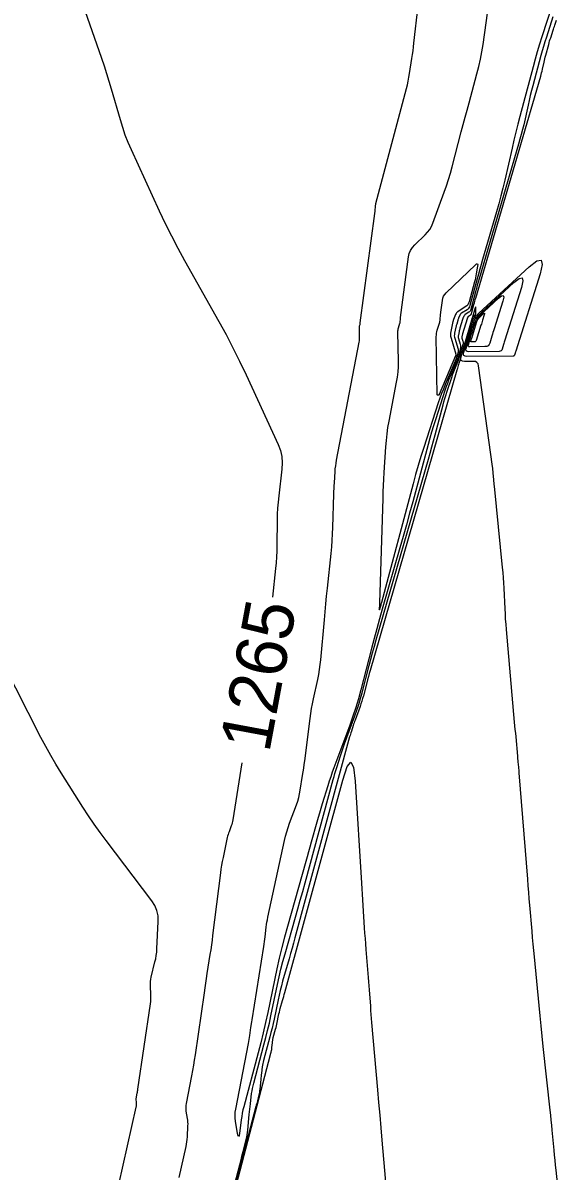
# Model space of a CAD drawing. Extents: x 658976 to 668726, y 639543 to 647196.
# Drawn here: x 661495.3 to 661559.5, y 640947.8 to 641084 of the extents above; entities that cross this region are included whole.
import ezdxf

# ---------------------------------------------------------------- set-up
doc = ezdxf.new("R2010")
doc.units = 0
for name, color, linetype in [('Ex_Contour Labels', 7, 'Continuous'), ('Ex_Major Contours', 7, 'Continuous'), ('Ex_Minor Contours', 7, 'Continuous')]:
    doc.layers.add(name, color=color, linetype=linetype)

msp = doc.modelspace()

# ---------------------------------------------------------------- linework, layer by layer
at = {"layer": 'Ex_Major Contours'}
for points in [[(661498.99, 641096.02), (661504.66, 641079.8), (661504.97, 641078.9), (661505.26, 641078), (661505.54, 641077.09), (661505.81, 641076.18), (661506.86, 641072.52), (661507.13, 641071.62), (661507.44, 641070.72), (661507.79, 641069.84), (661508.17, 641068.97), (661511.51, 641061.7), (661512.21, 641060.21), (661512.94, 641058.73), (661513.71, 641057.27), (661514.5, 641055.82), (661518.58, 641048.57), (661519.43, 641047.01), (661520.25, 641045.44), (661521.04, 641043.85), (661521.8, 641042.25), (661525.61, 641033.98), (661525.88, 641033.27), (661526.04, 641032.55), (661526.11, 641031.8), (661526.07, 641031.05), (661525.68, 641027.88), (661525.6, 641027.16), (661525.55, 641026.44), (661525.51, 641025.72), (661525.49, 641024.99), (661525.46, 641022.04), (661525.45, 641021.34), (661525.42, 641020.65), (661525.37, 641019.95), (661525.3, 641019.26), (661524.95, 641015.87)], [(661519.24, 640941.63), (661521.25, 640949.3), (661521.32, 640949.58), (661521.39, 640949.86), (661521.47, 640950.14), (661521.54, 640950.42), (661521.81, 640951.53), (661521.88, 640951.81), (661521.93, 640952.1), (661521.97, 640952.38), (661522, 640952.66), (661522.18, 640954.53), (661522.21, 640954.84), (661522.24, 640955.15), (661522.28, 640955.45), (661522.32, 640955.76), (661522.47, 640957), (661522.52, 640957.31), (661522.57, 640957.61), (661522.64, 640957.91), (661522.72, 640958.22), (661523.93, 640962.77), (661524.16, 640963.63), (661524.37, 640964.49), (661524.57, 640965.36), (661524.76, 640966.23), (661525.53, 640969.95), (661525.73, 640970.86), (661525.95, 640971.77), (661526.18, 640972.67), (661526.43, 640973.56), (661527.67, 640977.9), (661527.96, 640978.92), (661528.24, 640979.94), (661528.53, 640980.97), (661528.81, 640981.99), (661532.15, 640994.24), (661532.25, 640994.6), (661532.35, 640994.95), (661532.46, 640995.31), (661532.57, 640995.66), (661533.01, 640997.07), (661533.12, 640997.42), (661533.24, 640997.77), (661533.36, 640998.12), (661533.49, 640998.47), (661534.72, 641001.8), (661534.96, 641002.47), (661535.18, 641003.15), (661535.39, 641003.84), (661535.58, 641004.53), (661536.41, 641007.75), (661536.61, 641008.52), (661536.82, 641009.29), (661537.03, 641010.05), (661537.25, 641010.81), (661543.45, 641032.26), (661543.65, 641032.97), (661543.85, 641033.69), (661544.05, 641034.41), (661544.24, 641035.13), (661545.19, 641038.67), (661545.29, 641039.05), (661545.4, 641039.43), (661545.52, 641039.81), (661545.64, 641040.19), (661546.25, 641042.06), (661546.31, 641042.25), (661546.38, 641042.45), (661546.46, 641042.64), (661546.54, 641042.83), (661546.86, 641043.59), (661546.93, 641043.78), (661547, 641043.97), (661547.07, 641044.17), (661547.13, 641044.37), (661547.57, 641045.87), (661547.59, 641045.95), (661547.59, 641046.03), (661547.59, 641046.1), (661547.57, 641046.18), (661547.46, 641046.54), (661547.45, 641046.59), (661547.44, 641046.64), (661547.45, 641046.69), (661547.45, 641046.74), (661547.5, 641046.95), (661547.51, 641047), (661547.52, 641047.05), (661547.54, 641047.1), (661547.55, 641047.16), (661548.07, 641048.91), (661548.08, 641048.93), (661548.09, 641048.96), (661548.1, 641048.99), (661548.11, 641049.01), (661548.15, 641049.12), (661548.16, 641049.15), (661548.18, 641049.17), (661548.2, 641049.19), (661548.22, 641049.2), (661548.45, 641049.35), (661548.49, 641049.38), (661548.52, 641049.41), (661548.55, 641049.46), (661548.56, 641049.51), (661548.85, 641050.57), (661548.9, 641050.77), (661548.96, 641050.96), (661549.01, 641051.16), (661549.07, 641051.35), (661556.77, 641077.65), (661556.83, 641077.85), (661556.88, 641078.06), (661556.93, 641078.27), (661556.98, 641078.48), (661557.17, 641079.31), (661557.22, 641079.52), (661557.27, 641079.73), (661557.32, 641079.94), (661557.38, 641080.15), (661557.72, 641081.44), (661557.78, 641081.64), (661557.83, 641081.84), (661557.89, 641082.04), (661557.96, 641082.23), (661558.24, 641083.11), (661558.29, 641083.26), (661558.34, 641083.41), (661558.39, 641083.56), (661558.44, 641083.7), (661558.65, 641084.3)], [(661521.3, 640996.21), (661520.23, 640989.45), (661520.19, 640989.27), (661520.15, 640989.09), (661520.1, 640988.92), (661520.04, 640988.74), (661519.79, 640988.06), (661519.73, 640987.89), (661519.67, 640987.72), (661519.62, 640987.54), (661519.58, 640987.36), (661519.07, 640985), (661518.98, 640984.54), (661518.89, 640984.09), (661518.82, 640983.63), (661518.76, 640983.17), (661517.84, 640975.76), (661517.77, 640975.2), (661517.69, 640974.63), (661517.61, 640974.06), (661517.52, 640973.49), (661517.16, 640971.22), (661517.08, 640970.66), (661516.99, 640970.09), (661516.9, 640969.52), (661516.82, 640968.96), (661515.75, 640961.6), (661515.66, 640960.97), (661515.55, 640960.35), (661515.44, 640959.72), (661515.33, 640959.1), (661514.68, 640955.8), (661514.65, 640955.58), (661514.64, 640955.36), (661514.65, 640955.14), (661514.67, 640954.92), (661514.82, 640954.05), (661514.85, 640953.83), (661514.87, 640953.61), (661514.88, 640953.39), (661514.87, 640953.17), (661514.81, 640951.86), (661514.78, 640951.56), (661514.75, 640951.27), (661514.71, 640950.98), (661514.65, 640950.7), (661513.84, 640947.06)]]:
    msp.add_lwpolyline(points, dxfattribs=at)
msp.add_lwpolyline([(661553.79, 641044.99), (661553.77, 641044.93), (661553.75, 641044.87), (661553.73, 641044.81), (661553.66, 641044.58), (661553.64, 641044.53), (661553.61, 641044.49), (661553.56, 641044.47), (661553.5, 641044.46), (661548.02, 641044.41), (661547.8, 641044.44), (661547.66, 641044.53), (661547.6, 641044.7), (661547.64, 641044.92), (661548.59, 641048.25), (661548.61, 641048.33), (661548.64, 641048.4), (661548.66, 641048.47), (661548.68, 641048.54), (661548.77, 641048.83), (661548.8, 641048.9), (661548.83, 641048.97), (661548.87, 641049.03), (661548.93, 641049.08), (661555.4, 641055.05), (661556.31, 641055.76), (661556.82, 641055.85), (661556.95, 641055.34), (661556.7, 641054.22), (661553.81, 641045.05)], close=True, dxfattribs=at)
at = {"layer": 'Ex_Minor Contours'}
for points in [[(661558.2, 641086.31), (661556.92, 641082.35), (661556.63, 641081.46), (661556.36, 641080.57), (661556.11, 641079.67), (661555.86, 641078.77), (661554.3, 641072.9), (661554.05, 641071.97), (661553.81, 641071.02), (661553.58, 641070.08), (661553.37, 641069.13), (661552.51, 641065.34), (661552.29, 641064.4), (661552.05, 641063.46), (661551.8, 641062.52), (661551.54, 641061.59), (661549.88, 641055.92), (661549.71, 641055.34), (661549.55, 641054.77), (661549.39, 641054.19), (661549.23, 641053.61), (661548.38, 641050.45), (661548.33, 641050.3), (661548.25, 641050.18), (661548.15, 641050.07), (661548.03, 641049.97), (661547.37, 641049.55), (661547.3, 641049.5), (661547.25, 641049.45), (661547.2, 641049.38), (661547.16, 641049.3), (661547.03, 641048.99), (661547, 641048.91), (661546.97, 641048.83), (661546.95, 641048.75), (661546.92, 641048.67), (661546.8, 641048.27), (661546.78, 641048.18), (661546.75, 641048.08), (661546.73, 641047.99), (661546.71, 641047.89), (661546.55, 641047.18), (661546.53, 641047.03), (661546.52, 641046.88), (661546.54, 641046.73), (661546.57, 641046.58), (661546.96, 641045.3), (661546.98, 641045.21), (661546.99, 641045.11), (661546.98, 641045.01), (661546.96, 641044.92), (661546.85, 641044.53), (661546.82, 641044.43), (661546.79, 641044.34), (661546.75, 641044.24), (661546.72, 641044.15), (661545.44, 641041.11), (661545.22, 641040.56), (661545.01, 641040.02), (661544.81, 641039.47), (661544.62, 641038.92), (661542.89, 641033.63), (661542.55, 641032.56), (661542.23, 641031.48), (661541.91, 641030.41), (661541.62, 641029.32), (661537.87, 641015.26), (661537.86, 641015.23), (661537.86, 641015.2), (661537.85, 641015.17), (661537.84, 641015.14), (661537.81, 641015.03), (661537.8, 641015), (661537.79, 641014.97), (661537.78, 641014.94), (661537.78, 641014.91), (661537.66, 641014.45), (661537.64, 641014.38), (661537.63, 641014.36), (661537.62, 641014.39), (661537.63, 641014.45), (661537.68, 641014.99), (661537.68, 641015.01), (661537.68, 641015.03), (661537.68, 641015.04), (661537.68, 641015.06), (661537.69, 641015.13), (661537.69, 641015.15), (661537.69, 641015.17), (661537.69, 641015.18), (661537.69, 641015.2), (661538.07, 641027.58), (661538.09, 641028.35), (661538.13, 641029.12), (661538.16, 641029.88), (661538.21, 641030.65), (661538.4, 641033.71), (661538.46, 641034.47), (661538.55, 641035.23), (661538.65, 641035.99), (661538.79, 641036.75), (661539.67, 641041.36), (661539.77, 641041.98), (661539.84, 641042.59), (661539.88, 641043.21), (661539.88, 641043.83), (661539.82, 641047.34), (661539.83, 641047.46), (661539.84, 641047.57), (661539.86, 641047.69), (661539.89, 641047.8), (661540.06, 641048.36), (661540.08, 641048.42), (661540.09, 641048.47), (661540.1, 641048.53), (661540.1, 641048.58), (661540.12, 641048.81), (661540.12, 641048.87), (661540.13, 641048.93), (661540.13, 641048.98), (661540.14, 641049.04), (661541.09, 641056.22), (661541.18, 641056.62), (661541.33, 641057), (661541.54, 641057.34), (661541.82, 641057.65), (661543.06, 641058.84), (661543.35, 641059.15), (661543.6, 641059.48), (661543.8, 641059.84), (661543.97, 641060.23), (661545.31, 641063.9), (661545.58, 641064.65), (661545.82, 641065.41), (661546.05, 641066.17), (661546.26, 641066.93), (661547.35, 641071.08), (661547.58, 641071.94), (661547.81, 641072.79), (661548.04, 641073.65), (661548.27, 641074.51), (661549.21, 641077.94), (661549.43, 641078.8), (661549.63, 641079.67), (661549.79, 641080.54), (661549.93, 641081.42), (661550.8, 641087.74)], [(661558.22, 641084.71), (661557.44, 641082.29), (661557.26, 641081.75), (661557.1, 641081.2), (661556.94, 641080.66), (661556.79, 641080.11), (661555.84, 641076.53), (661555.69, 641075.95), (661555.54, 641075.38), (661555.4, 641074.8), (661555.27, 641074.22), (661554.75, 641071.91), (661554.61, 641071.33), (661554.47, 641070.76), (661554.31, 641070.19), (661554.15, 641069.62), (661549.47, 641053.63), (661549.36, 641053.25), (661549.25, 641052.87), (661549.14, 641052.48), (661549.04, 641052.09), (661548.47, 641049.98), (661548.44, 641049.88), (661548.39, 641049.8), (661548.32, 641049.72), (661548.24, 641049.66), (661547.8, 641049.38), (661547.75, 641049.34), (661547.71, 641049.31), (661547.68, 641049.26), (661547.66, 641049.21), (661547.57, 641049), (661547.55, 641048.95), (661547.53, 641048.9), (661547.51, 641048.84), (661547.5, 641048.79), (661547.19, 641047.77), (661547.16, 641047.67), (661547.14, 641047.57), (661547.11, 641047.47), (661547.09, 641047.37), (661547, 641046.96), (661546.99, 641046.86), (661546.98, 641046.76), (661546.99, 641046.66), (661547.02, 641046.56), (661547.23, 641045.87), (661547.26, 641045.72), (661547.27, 641045.57), (661547.26, 641045.42), (661547.23, 641045.27), (661547.01, 641044.51), (661546.95, 641044.33), (661546.89, 641044.16), (661546.83, 641043.98), (661546.76, 641043.81), (661545.99, 641041.97), (661545.84, 641041.6), (661545.7, 641041.23), (661545.56, 641040.86), (661545.43, 641040.49), (661544.27, 641036.91), (661544.04, 641036.18), (661543.81, 641035.46), (661543.6, 641034.73), (661543.4, 641034), (661541.59, 641027.2), (661541.22, 641025.82), (661540.85, 641024.45), (661540.46, 641023.08), (661540.07, 641021.71), (661537.97, 641014.46), (661537.64, 641013.29), (661537.32, 641012.13), (661537, 641010.96), (661536.69, 641009.79), (661535.42, 641004.87), (661535.14, 641003.82), (661534.82, 641002.78), (661534.48, 641001.74), (661534.12, 641000.71), (661532.23, 640995.63), (661532.04, 640995.1), (661531.86, 640994.57), (661531.68, 640994.04), (661531.51, 640993.5), (661530.83, 640991.35), (661530.67, 640990.81), (661530.51, 640990.27), (661530.35, 640989.73), (661530.2, 640989.19), (661529.55, 640986.81), (661529.39, 640986.24), (661529.23, 640985.66), (661529.07, 640985.09), (661528.91, 640984.51), (661526.71, 640976.81), (661526.36, 640975.56), (661526.04, 640974.31), (661525.74, 640973.06), (661525.47, 640971.8), (661524.39, 640966.62), (661524.13, 640965.42), (661523.85, 640964.22), (661523.56, 640963.02), (661523.25, 640961.83), (661521.54, 640955.43), (661521.44, 640955.05), (661521.36, 640954.67), (661521.29, 640954.28), (661521.23, 640953.9), (661521.02, 640952.28), (661520.97, 640952.01), (661520.92, 640951.92), (661520.87, 640952), (661520.81, 640952.27), (661520.56, 640953.71), (661520.52, 640954.06), (661520.51, 640954.42), (661520.53, 640954.78), (661520.58, 640955.14), (661522.1, 640962.95), (661522.14, 640963.18), (661522.18, 640963.41), (661522.22, 640963.65), (661522.26, 640963.88), (661522.39, 640964.82), (661522.43, 640965.05), (661522.46, 640965.29), (661522.5, 640965.52), (661522.54, 640965.75), (661523.9, 640974.45), (661523.94, 640974.73), (661523.98, 640975.02), (661524.02, 640975.31), (661524.06, 640975.6), (661524.2, 640976.75), (661524.24, 640977.04), (661524.29, 640977.33), (661524.34, 640977.61), (661524.4, 640977.9), (661526.37, 640987), (661526.49, 640987.52), (661526.63, 640988.04), (661526.79, 640988.55), (661526.97, 640989.06), (661527.79, 640991.26), (661527.94, 640991.68), (661528.06, 640992.1), (661528.16, 640992.53), (661528.24, 640992.97), (661528.52, 640994.72), (661528.59, 640995.16), (661528.65, 640995.6), (661528.71, 640996.04), (661528.77, 640996.48), (661529.4, 641001.48), (661529.48, 641002.07), (661529.57, 641002.65), (661529.68, 641003.23), (661529.8, 641003.81), (661530.31, 641006.12), (661530.43, 641006.7), (661530.53, 641007.28), (661530.61, 641007.87), (661530.67, 641008.45), (661531.1, 641013.18), (661531.19, 641014.12), (661531.28, 641015.07), (661531.37, 641016.01), (661531.47, 641016.95), (661531.9, 641021.07), (661531.97, 641021.84), (661532.03, 641022.6), (661532.08, 641023.37), (661532.11, 641024.14), (661532.23, 641028.07), (661532.24, 641028.41), (661532.25, 641028.75), (661532.27, 641029.09), (661532.29, 641029.42), (661532.37, 641030.77), (661532.4, 641031.11), (661532.44, 641031.45), (661532.48, 641031.78), (661532.54, 641032.11), (661535.22, 641046.1), (661535.25, 641046.29), (661535.27, 641046.47), (661535.28, 641046.66), (661535.28, 641046.85), (661535.26, 641047.91), (661535.27, 641047.94), (661535.27, 641047.98), (661535.28, 641048.01), (661535.28, 641048.05), (661535.34, 641048.22), (661535.34, 641048.23), (661535.35, 641048.25), (661535.35, 641048.27), (661535.35, 641048.29), (661535.35, 641048.35), (661535.35, 641048.37), (661535.36, 641048.39), (661535.36, 641048.41), (661535.36, 641048.42), (661537.08, 641061.39), (661537.09, 641061.49), (661537.11, 641061.58), (661537.11, 641061.68), (661537.12, 641061.78), (661537.15, 641062.17), (661537.16, 641062.27), (661537.17, 641062.37), (661537.19, 641062.46), (661537.21, 641062.56), (661540.84, 641076.21), (661540.96, 641076.65), (661541.05, 641077.09), (661541.14, 641077.54), (661541.22, 641077.98), (661541.49, 641079.78), (661541.56, 641080.23), (661541.62, 641080.68), (661541.68, 641081.13), (661541.73, 641081.59), (661542.23, 641085.99)], [(661559.54, 640939), (661558.59, 640947.93), (661558.52, 640948.52), (661558.47, 640949.11), (661558.41, 640949.7), (661558.35, 640950.3), (661558.13, 640952.66), (661558.08, 640953.26), (661558.02, 640953.85), (661557.96, 640954.44), (661557.9, 640955.03), (661557.07, 640962.59), (661556.94, 640963.81), (661556.81, 640965.02), (661556.69, 640966.23), (661556.57, 640967.45), (661556.02, 640973.2), (661555.95, 640973.97), (661555.88, 640974.73), (661555.81, 640975.5), (661555.75, 640976.27), (661555.49, 640979.34), (661555.42, 640980.11), (661555.36, 640980.87), (661555.3, 640981.64), (661555.24, 640982.41), (661554.23, 640995.05), (661554.22, 640995.22), (661554.2, 640995.38), (661554.19, 640995.54), (661554.17, 640995.71), (661554.11, 640996.36), (661554.09, 640996.52), (661554.07, 640996.69), (661554.06, 640996.85), (661554.04, 640997.01), (661553.84, 640999.31), (661553.8, 640999.75), (661553.76, 641000.19), (661553.72, 641000.63), (661553.68, 641001.06), (661552.71, 641012.05), (661552.66, 641012.66), (661552.61, 641013.28), (661552.58, 641013.89), (661552.54, 641014.5), (661552.43, 641016.96), (661552.4, 641017.57), (661552.36, 641018.18), (661552.31, 641018.8), (661552.25, 641019.41), (661551.28, 641029.04), (661551.26, 641029.23), (661551.24, 641029.43), (661551.22, 641029.62), (661551.2, 641029.82), (661551.14, 641030.6), (661551.12, 641030.79), (661551.1, 641030.99), (661551.08, 641031.18), (661551.05, 641031.38), (661549.4, 641043.31), (661549.34, 641043.54), (661549.21, 641043.71), (661549.03, 641043.81), (661548.79, 641043.84), (661547.71, 641043.83), (661547.48, 641043.86), (661547.34, 641043.95), (661547.28, 641044.11), (661547.31, 641044.34), (661548.66, 641049.01), (661548.66, 641049.02), (661548.66, 641049.03), (661548.66, 641049.03), (661548.97, 641049.32), (661549.02, 641049.37), (661549.05, 641049.42), (661549.07, 641049.49), (661549.08, 641049.55), (661549.07, 641050.17), (661549.06, 641050.27), (661549.04, 641050.3), (661549.02, 641050.27), (661548.99, 641050.18), (661548.66, 641049.07), (661548.66, 641049.06), (661548.66, 641049.04), (661548.65, 641049.03), (661548.65, 641049.03), (661548.65, 641049.02), (661547.91, 641046.54), (661547.91, 641046.53), (661547.91, 641046.52), (661547.9, 641046.52), (661547.91, 641046.51), (661547.91, 641046.49), (661547.91, 641046.49), (661547.91, 641046.49), (661547.91, 641046.48), (661547.91, 641046.48), (661547.14, 641043.82), (661547.13, 641043.8), (661547.13, 641043.79), (661547.12, 641043.77), (661547.11, 641043.75), (661547.09, 641043.69), (661547.08, 641043.68), (661547.07, 641043.66), (661547.07, 641043.64), (661547.06, 641043.63), (661547.01, 641043.47), (661547, 641043.44), (661546.99, 641043.41), (661546.98, 641043.38), (661546.97, 641043.35), (661546.9, 641043.05), (661546.88, 641042.99), (661546.86, 641042.93), (661546.85, 641042.87), (661546.83, 641042.81), (661536.53, 641007.17), (661536.42, 641006.81), (661536.32, 641006.45), (661536.22, 641006.08), (661536.13, 641005.72), (661535.73, 641004.18), (661535.64, 641003.86), (661535.55, 641003.53), (661535.44, 641003.21), (661535.33, 641002.89), (661534.74, 641001.3), (661534.68, 641001.14), (661534.62, 641000.97), (661534.56, 641000.8), (661534.51, 641000.64), (661534.3, 640999.97), (661534.25, 640999.8), (661534.2, 640999.63), (661534.15, 640999.46), (661534.1, 640999.29), (661527.61, 640975.48), (661527.43, 640974.85), (661527.26, 640974.23), (661527.08, 640973.6), (661526.91, 640972.98), (661526.15, 640970.32), (661526, 640969.77), (661525.85, 640969.22), (661525.72, 640968.67), (661525.6, 640968.11), (661525.13, 640965.83), (661525.01, 640965.3), (661524.89, 640964.77), (661524.76, 640964.24), (661524.62, 640963.71), (661523.88, 640960.92), (661523.83, 640960.74), (661523.79, 640960.55), (661523.76, 640960.37), (661523.73, 640960.18), (661523.63, 640959.42), (661523.61, 640959.23), (661523.59, 640959.04), (661523.56, 640958.85), (661523.55, 640958.66), (661523.44, 640957.52), (661523.42, 640957.35), (661523.39, 640957.18), (661523.36, 640957), (661523.32, 640956.83), (661523.15, 640956.15), (661523.11, 640955.98), (661523.07, 640955.81), (661523.02, 640955.64), (661522.98, 640955.47), (661518.15, 640937.05)], [(661506.72, 640946.21), (661508.77, 640955.39), (661508.78, 640955.44), (661508.79, 640955.5), (661508.79, 640955.56), (661508.8, 640955.61), (661508.81, 640955.87), (661508.81, 640955.92), (661508.81, 640955.96), (661508.81, 640956), (661508.8, 640956.04), (661508.77, 640956.22), (661508.76, 640956.26), (661508.76, 640956.3), (661508.77, 640956.34), (661508.77, 640956.39), (661508.9, 640957.03), (661508.92, 640957.16), (661508.94, 640957.28), (661508.96, 640957.4), (661508.98, 640957.53), (661510.45, 640967.65), (661510.49, 640967.91), (661510.51, 640968.17), (661510.51, 640968.44), (661510.5, 640968.7), (661510.45, 640969.77), (661510.45, 640970.03), (661510.46, 640970.29), (661510.5, 640970.55), (661510.55, 640970.81), (661510.99, 640972.61), (661511.08, 640972.99), (661511.15, 640973.38), (661511.2, 640973.78), (661511.22, 640974.17), (661511.38, 640977.42), (661511.36, 640978.08), (661511.22, 640978.7), (661510.98, 640979.29), (661510.63, 640979.85), (661505.21, 640987), (661504.49, 640987.97), (661503.79, 640988.95), (661503.11, 640989.95), (661502.45, 640990.96), (661499.86, 640995.03), (661499.23, 640996.06), (661498.62, 640997.1), (661498.03, 640998.15), (661497.47, 640999.22), (661492.98, 641008.03)], [(661517.06, 640932.47), (661524.71, 640961.63), (661524.72, 640961.69), (661524.74, 640961.76), (661524.76, 640961.82), (661524.77, 640961.88), (661524.83, 640962.13), (661524.85, 640962.19), (661524.86, 640962.26), (661524.87, 640962.32), (661524.88, 640962.38), (661524.92, 640962.8), (661524.92, 640962.87), (661524.93, 640962.94), (661524.94, 640963.01), (661524.95, 640963.08), (661524.98, 640963.36), (661524.99, 640963.43), (661525, 640963.5), (661525.02, 640963.56), (661525.04, 640963.63), (661525.31, 640964.65), (661525.36, 640964.85), (661525.41, 640965.04), (661525.45, 640965.23), (661525.49, 640965.43), (661525.67, 640966.27), (661525.71, 640966.47), (661525.76, 640966.67), (661525.81, 640966.88), (661525.87, 640967.08), (661526.15, 640968.05), (661526.21, 640968.28), (661526.28, 640968.51), (661526.34, 640968.74), (661526.4, 640968.97), (661533.28, 640994.18), (661533.82, 640995.8), (661534.24, 640996.31), (661534.55, 640995.72), (661534.74, 640994.04), (661535.5, 640981.94), (661535.54, 640981.28), (661535.58, 640980.63), (661535.62, 640979.97), (661535.66, 640979.31), (661535.84, 640976.65), (661535.88, 640976.01), (661535.93, 640975.37), (661535.98, 640974.74), (661536.03, 640974.1), (661536.27, 640971.23), (661536.31, 640970.75), (661536.35, 640970.26), (661536.39, 640969.78), (661536.42, 640969.29), (661536.56, 640967.35), (661536.59, 640966.86), (661536.63, 640966.38), (661536.67, 640965.89), (661536.71, 640965.41), (661537.41, 640957.43), (661537.54, 640955.93), (661537.67, 640954.44), (661537.79, 640952.95), (661537.92, 640951.46), (661538.97, 640939.33)]]:
    msp.add_lwpolyline(points, dxfattribs=at)
for points in [[(661545.16, 641051.32), (661545.25, 641051.56), (661545.39, 641051.77), (661545.56, 641051.97), (661549.03, 641055.28), (661549.17, 641055.39), (661549.26, 641055.41), (661549.3, 641055.32), (661549.29, 641055.14), (661549.13, 641054.21), (661549.09, 641053.98), (661549.04, 641053.75), (661548.98, 641053.52), (661548.93, 641053.29), (661548.29, 641050.92), (661548.22, 641050.73), (661548.12, 641050.56), (661547.99, 641050.41), (661547.82, 641050.29), (661546.94, 641049.73), (661546.85, 641049.66), (661546.78, 641049.58), (661546.72, 641049.5), (661546.67, 641049.4), (661546.43, 641048.81), (661546.42, 641048.79), (661546.41, 641048.77), (661546.4, 641048.75), (661546.4, 641048.73), (661546.37, 641048.64), (661546.37, 641048.62), (661546.36, 641048.6), (661546.36, 641048.58), (661546.35, 641048.56), (661546.1, 641047.4), (661546.07, 641047.2), (661546.06, 641047), (661546.08, 641046.81), (661546.13, 641046.61), (661546.71, 641044.69), (661546.72, 641044.67), (661546.72, 641044.65), (661546.72, 641044.64), (661546.71, 641044.62), (661546.69, 641044.55), (661546.69, 641044.54), (661546.68, 641044.52), (661546.68, 641044.51), (661546.67, 641044.49), (661544.74, 641039.9), (661544.73, 641039.88), (661544.71, 641039.86), (661544.69, 641039.85), (661544.66, 641039.84), (661544.55, 641039.83), (661544.53, 641039.83), (661544.51, 641039.84), (661544.5, 641039.86), (661544.5, 641039.88), (661544.38, 641046.77), (661544.39, 641046.97), (661544.41, 641047.17), (661544.44, 641047.36), (661544.49, 641047.55), (661544.79, 641048.5), (661544.82, 641048.6), (661544.84, 641048.69), (661544.85, 641048.79), (661544.86, 641048.88), (661544.88, 641049.27), (661544.89, 641049.37), (661544.89, 641049.47), (661544.9, 641049.56), (661544.92, 641049.66), (661545.1, 641051.06)], [(661552.48, 641046.23), (661552.44, 641046.1), (661552.4, 641045.96), (661552.36, 641045.83), (661552.19, 641045.3), (661552.14, 641045.18), (661552.06, 641045.1), (661551.96, 641045.04), (661551.83, 641045.03), (661548.19, 641044.99), (661548.03, 641045.01), (661547.93, 641045.08), (661547.89, 641045.19), (661547.91, 641045.35), (661548.53, 641047.5), (661548.57, 641047.64), (661548.61, 641047.79), (661548.66, 641047.93), (661548.7, 641048.07), (661548.88, 641048.65), (661548.93, 641048.78), (661549, 641048.91), (661549.09, 641049.03), (661549.19, 641049.13), (661553.58, 641053.18), (661554.22, 641053.68), (661554.58, 641053.75), (661554.67, 641053.39), (661554.49, 641052.61), (661552.52, 641046.36)], [(661551.18, 641047.47), (661551.11, 641047.26), (661551.05, 641047.05), (661550.98, 641046.84), (661550.72, 641046.01), (661550.64, 641045.83), (661550.52, 641045.7), (661550.36, 641045.62), (661550.16, 641045.59), (661548.35, 641045.57), (661548.26, 641045.58), (661548.2, 641045.62), (661548.18, 641045.69), (661548.19, 641045.78), (661548.53, 641046.98), (661548.56, 641047.08), (661548.59, 641047.17), (661548.62, 641047.27), (661548.65, 641047.36), (661548.99, 641048.46), (661549.07, 641048.66), (661549.17, 641048.85), (661549.3, 641049.03), (661549.45, 641049.19), (661551.76, 641051.32), (661552.13, 641051.6), (661552.33, 641051.64), (661552.39, 641051.44), (661552.29, 641050.99), (661551.24, 641047.68)], [(661549.83, 641048.58), (661549.78, 641048.43), (661549.73, 641048.27), (661549.68, 641048.12), (661549.12, 641046.31), (661549.09, 641046.24), (661549.05, 641046.19), (661548.99, 641046.17), (661548.92, 641046.16), (661548.51, 641046.15), (661548.48, 641046.15), (661548.47, 641046.16), (661548.46, 641046.18), (661548.47, 641046.2), (661548.55, 641046.51), (661548.56, 641046.53), (661548.57, 641046.56), (661548.58, 641046.58), (661548.58, 641046.61), (661549.19, 641048.55), (661549.24, 641048.69), (661549.31, 641048.82), (661549.4, 641048.94), (661549.5, 641049.04), (661549.95, 641049.46), (661550.04, 641049.53), (661550.09, 641049.54), (661550.1, 641049.49), (661550.08, 641049.37), (661549.88, 641048.73)]]:
    msp.add_lwpolyline(points, close=True, dxfattribs=at)

# ---------------------------------------------------------------- texts
at = {"layer": 'Ex_Contour Labels'}
msp.add_text('1265', height=6, rotation=79.4733, dxfattribs=at).set_placement((661524.55, 640997.3))

doc.saveas('drawing.dxf')
